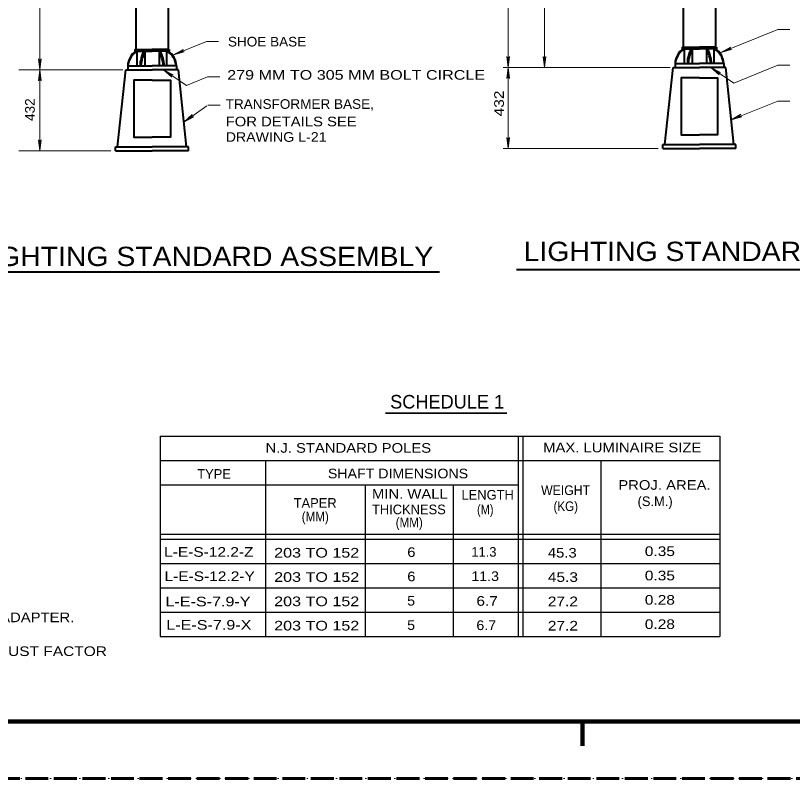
# Model space of a CAD drawing. Extents: x 312583 to 312854, y 144419 to 144597.
# Drawn here: x 312682.7 to 312743.9, y 144418.6 to 144478.7 of the extents above; entities that cross this region are included whole.
import ezdxf
from ezdxf.enums import TextEntityAlignment as Align

# ---------------------------------------------------------------- set-up
doc = ezdxf.new("R2010")
doc.units = 0
doc.header["$LTSCALE"] = 0.3
doc.linetypes.add('DOTTED', pattern=[1.5, 0.3, -1.2])
doc.linetypes.add('LONG_DASHED', pattern=[7.5, 6, -1.5])
for name, color, linetype, lineweight in [('1', 7, 'Continuous', 40), ('2', 7, 'Continuous', 13), ('63', 7, 'DOTTED', 13)]:
    doc.layers.add(name, color=color, linetype=linetype, lineweight=lineweight)

msp = doc.modelspace()

# ---------------------------------------------------------------- linework, layer by layer
at = {"layer": '1'}
for p, q in [((312692.1518, 144520.4576), (312692.1518, 144476.0523)), ((312694.7125, 144520.4576), (312694.7125, 144476.0523)), ((312735.288, 144495.6943), (312735.288, 144476.2363)), ((312737.8487, 144495.6943), (312737.8487, 144476.2363)), ((312692.0752, 144476.0523), (312693.4322, 144476.0523)), ((312692.0752, 144476.0523), (312692.0752, 144475.9373)), ((312694.7892, 144476.0523), (312693.4322, 144476.0523)), ((312694.7892, 144476.0523), (312694.7892, 144475.9373)), ((312735.2113, 144476.2363), (312736.5683, 144476.2363)), ((312735.2113, 144476.2363), (312735.2113, 144476.1213)), ((312735.2113, 144476.1213), (312736.5683, 144476.1213)), ((312735.3953, 144474.9636), (312735.3953, 144476.1213)), ((312736.0087, 144476.1213), (312736.0087, 144475.002)), ((312737.9253, 144476.2363), (312736.5683, 144476.2363)), ((312737.9253, 144476.1213), (312736.5683, 144476.1213)), ((312737.128, 144476.1213), (312737.128, 144475.002)), ((312737.7413, 144474.9636), (312737.7413, 144476.1213)), ((312737.9253, 144476.2363), (312737.9253, 144476.1213)), ((312692.0752, 144475.9373), (312693.4322, 144475.9373)), ((312692.2592, 144474.7796), (312692.2592, 144475.9373)), ((312692.8725, 144475.9373), (312692.8725, 144474.818)), ((312694.7892, 144475.9373), (312693.4322, 144475.9373)), ((312693.9918, 144475.9373), (312693.9918, 144474.818)), ((312694.6052, 144474.7796), (312694.6052, 144475.9373)), ((312691.5155, 144474.7796), (312693.4322, 144474.7796)), ((312691.5155, 144474.7796), (312691.5155, 144474.4576)), ((312695.3488, 144474.7796), (312693.4322, 144474.7796)), ((312695.3488, 144474.7796), (312695.3488, 144474.4576)), ((312734.6517, 144474.9636), (312736.5683, 144474.9636)), ((312734.6517, 144474.9636), (312734.6517, 144474.6416)), ((312738.485, 144474.9636), (312736.5683, 144474.9636)), ((312738.485, 144474.9636), (312738.485, 144474.6416)), ((312690.7182, 144468.3856), (312691.3545, 144474.4576)), ((312691.3545, 144474.4576), (312693.4322, 144474.4576)), ((312695.5098, 144474.4576), (312693.4322, 144474.4576)), ((312696.1462, 144468.3856), (312695.5098, 144474.4576)), ((312733.8543, 144468.5696), (312734.4907, 144474.6416)), ((312734.4907, 144474.6416), (312736.5683, 144474.6416)), ((312738.646, 144474.6416), (312736.5683, 144474.6416)), ((312739.2823, 144468.5696), (312738.646, 144474.6416)), ((312690.5572, 144468.3856), (312693.4322, 144468.3856)), ((312690.5572, 144468.0713), (312690.5572, 144468.3856)), ((312690.5572, 144468.0713), (312693.4322, 144468.0713)), ((312696.3072, 144468.3856), (312693.4322, 144468.3856)), ((312696.3072, 144468.0713), (312693.4322, 144468.0713)), ((312696.3072, 144468.0713), (312696.3072, 144468.3856)), ((312733.6933, 144468.5696), (312736.5683, 144468.5696)), ((312733.6933, 144468.2553), (312733.6933, 144468.5696)), ((312733.6933, 144468.2553), (312736.5683, 144468.2553)), ((312739.4433, 144468.5696), (312736.5683, 144468.5696)), ((312739.4433, 144468.2553), (312736.5683, 144468.2553)), ((312739.4433, 144468.2553), (312739.4433, 144468.5696))]:
    msp.add_line(p, q, dxfattribs=at)
at = {"layer": '1', "lineweight": 158}
for p, q in [((312616.5, 144423.0846), (312849, 144423.0846)), ((312727.35, 144421.1646), (312727.35, 144423.0846))]:
    msp.add_line(p, q, dxfattribs=at)
at = {"layer": '1'}
for points in [[(312693.4322, 144473.6296), (312691.9985, 144473.6296), (312691.9985, 144469.1523), (312693.4322, 144469.1523)], [(312693.4322, 144473.6296), (312694.8735, 144473.6296), (312694.8735, 144469.1523), (312693.4322, 144469.1523)], [(312736.5683, 144473.8136), (312735.127, 144473.8136), (312735.127, 144469.3363), (312736.5683, 144469.3363)], [(312736.5683, 144473.8136), (312738.002, 144473.8136), (312738.002, 144469.3363), (312736.5683, 144469.3363)]]:
    msp.add_lwpolyline(points, dxfattribs=at)
for centre, radius, start, end in [((312736.1161, 144474.907), 1.4657, 124.21849, 177.88724), ((312736.2591, 144474.748), 1.6218, 122.28719, 172.4519), ((312738.5681, 144474.79), 2.9635, 153.35491, 176.59885), ((312738.5681, 144474.79), 2.8836, 152.55593, 176.59975), ((312734.5679, 144474.79), 2.8836, 3.40025, 27.44407), ((312734.5679, 144474.79), 2.9635, 3.40115, 26.64509), ((312736.877, 144474.748), 1.6218, 7.5481, 57.71281), ((312737.0199, 144474.907), 1.4657, 2.11276, 55.78151), ((312693.1235, 144474.5631), 1.6218, 122.28719, 172.4519), ((312692.9806, 144474.7221), 1.4657, 124.21849, 177.88724), ((312695.4326, 144474.6051), 2.9635, 153.35491, 176.59885), ((312695.4326, 144474.6051), 2.8836, 152.55593, 176.59975), ((312691.4324, 144474.6051), 2.8836, 3.40025, 27.44407), ((312691.4324, 144474.6051), 2.9635, 3.40115, 26.64509), ((312693.7414, 144474.5631), 1.6218, 7.5481, 57.71281), ((312693.8844, 144474.7221), 1.4657, 2.11276, 55.78151), ((312692.9134, 144474.8161), 0.0399, 180, 270), ((312693.9516, 144474.8161), 0.0399, 270, 0), ((312736.0489, 144475.001), 0.0399, 180, 270), ((312737.0871, 144475.001), 0.0399, 270, 0)]:
    msp.add_arc(centre, radius, start, end, dxfattribs=at)
at = {"layer": '2'}
for p, q in [((312684.596, 144474.4576), (312684.596, 144558.791)), ((312721.4957, 144474.6416), (312721.4957, 144558.975)), ((312724.3707, 144474.6416), (312724.3707, 144520.6416)), ((312738.255, 144475.8223), (312742.7477, 144477.6316)), ((312742.7477, 144477.6316), (312743.706, 144477.6316)), ((312695.1188, 144475.6383), (312697.717, 144476.6847)), ((312697.717, 144476.6847), (312698.6753, 144476.6847)), ((312695.1188, 144475.6383), (312695.8855, 144476.06)), ((312695.8855, 144476.06), (312695.6708, 144475.8606)), ((312738.255, 144475.8223), (312739.0217, 144476.2516)), ((312738.255, 144475.8223), (312739.0983, 144476.0523)), ((312739.0217, 144476.2516), (312738.807, 144476.0446)), ((312739.0983, 144476.0523), (312738.807, 144476.0446)), ((312695.1188, 144475.6383), (312695.9622, 144475.8606)), ((312695.9622, 144475.8606), (312695.6708, 144475.8606)), ((312721.3883, 144475.508), (312721.4957, 144475.232)), ((312721.4957, 144474.6416), (312721.3883, 144475.508)), ((312721.603, 144475.508), (312721.4957, 144475.232)), ((312721.4957, 144474.6416), (312721.603, 144475.508)), ((312724.2633, 144475.508), (312724.3707, 144475.232)), ((312724.3707, 144474.6416), (312724.2633, 144475.508)), ((312724.478, 144475.508), (312724.3707, 144475.232)), ((312724.3707, 144474.6416), (312724.478, 144475.508)), ((312684.4887, 144475.324), (312684.596, 144475.048)), ((312684.596, 144474.4576), (312684.4887, 144475.324)), ((312684.7033, 144475.324), (312684.596, 144475.048)), ((312684.596, 144474.4576), (312684.7033, 144475.324)), ((312739.2747, 144473.415), (312742.7477, 144474.818)), ((312742.7477, 144474.818), (312743.706, 144474.818)), ((312691.1322, 144474.4576), (312682.9368, 144474.4576)), ((312684.596, 144474.4576), (312684.4887, 144473.5913)), ((312684.596, 144468.0713), (312684.596, 144474.4576)), ((312684.596, 144474.4576), (312684.7033, 144473.5913)), ((312696.1385, 144473.231), (312694.3292, 144474.4576)), ((312694.3292, 144474.4576), (312694.9808, 144473.8826)), ((312694.3292, 144474.4576), (312695.1035, 144474.059)), ((312694.9808, 144473.8826), (312694.8122, 144474.128)), ((312695.1035, 144474.059), (312694.8122, 144474.128)), ((312734.2683, 144474.6416), (312721.1123, 144474.6416)), ((312721.4957, 144474.6416), (312721.3883, 144473.7753)), ((312721.4957, 144468.2553), (312721.4957, 144474.6416)), ((312721.4957, 144474.6416), (312721.603, 144473.7753)), ((312739.2747, 144473.415), (312737.4653, 144474.6416)), ((312737.4653, 144474.6416), (312738.117, 144474.0666)), ((312737.4653, 144474.6416), (312738.2397, 144474.243)), ((312738.117, 144474.0666), (312737.9483, 144474.312)), ((312738.2397, 144474.243), (312737.9483, 144474.312)), ((312684.4887, 144473.5913), (312684.596, 144473.8673)), ((312684.7033, 144473.5913), (312684.596, 144473.8673)), ((312696.1385, 144473.231), (312697.8078, 144473.9053)), ((312697.8078, 144473.9053), (312698.7661, 144473.9053)), ((312721.3883, 144473.7753), (312721.4957, 144474.0513)), ((312721.603, 144473.7753), (312721.4957, 144474.0513)), ((312697.8398, 144471.6784), (312698.7981, 144471.6784)), ((312739.0753, 144470.517), (312742.7477, 144471.9966)), ((312742.7477, 144471.9966), (312743.706, 144471.9966)), ((312695.9392, 144470.333), (312697.7438, 144471.6215)), ((312695.9392, 144470.333), (312696.5908, 144470.9233)), ((312695.9392, 144470.333), (312696.7135, 144470.747)), ((312696.5908, 144470.9233), (312696.4298, 144470.6703)), ((312696.7135, 144470.747), (312696.4298, 144470.6703)), ((312739.0753, 144470.517), (312739.842, 144470.9463)), ((312739.0753, 144470.517), (312739.9187, 144470.747)), ((312739.842, 144470.9463), (312739.6273, 144470.7393)), ((312739.9187, 144470.747), (312739.6273, 144470.7393)), ((312684.4887, 144468.9376), (312684.596, 144468.6616)), ((312684.596, 144468.0713), (312684.4887, 144468.9376)), ((312684.7033, 144468.9376), (312684.596, 144468.6616)), ((312684.596, 144468.0713), (312684.7033, 144468.9376)), ((312721.3883, 144469.1216), (312721.4957, 144468.8456)), ((312721.4957, 144468.2553), (312721.3883, 144469.1216)), ((312721.603, 144469.1216), (312721.4957, 144468.8456)), ((312721.4957, 144468.2553), (312721.603, 144469.1216)), ((312690.1738, 144468.0713), (312682.9368, 144468.0713)), ((312733.31, 144468.2553), (312721.1123, 144468.2553))]:
    msp.add_line(p, q, dxfattribs=at)
at = {"layer": '2', "lineweight": 40}
for p, q in [((312679.0175, 144458.5382), (312716.0815, 144458.5382)), ((312722.1455, 144458.7223), (312759.4221, 144458.7223))]:
    msp.add_line(p, q, dxfattribs=at)
at = {"layer": '2', "lineweight": 35}
msp.add_line((312711.8273, 144447.398), (312721.3945, 144447.398), dxfattribs=at)
at = {"layer": '2', "lineweight": 25}
for p, q in [((312694.0795, 144445.5734), (312738.1839, 144445.5734)), ((312722.2755, 144445.5734), (312722.2755, 144429.7867)), ((312722.6589, 144445.5734), (312722.6589, 144429.7867)), ((312738.1839, 144445.5734), (312738.1839, 144429.7867)), ((312694.0795, 144443.6567), (312738.1839, 144443.6567)), ((312702.3702, 144443.6567), (312702.3702, 144429.7867)), ((312728.7922, 144443.6567), (312728.7922, 144429.7867)), ((312694.0795, 144441.74), (312722.2755, 144441.74)), ((312710.2366, 144441.74), (312710.2366, 144429.7867)), ((312717.1584, 144441.74), (312717.1584, 144429.7867)), ((312694.0795, 144437.8367), (312738.1839, 144437.8367)), ((312694.0795, 144437.4534), (312738.1839, 144437.4534)), ((312694.0795, 144435.5367), (312738.1839, 144435.5367)), ((312694.0795, 144433.62), (312738.1839, 144433.62)), ((312694.0795, 144431.7034), (312738.1839, 144431.7034))]:
    msp.add_line(p, q, dxfattribs=at)
msp.add_lwpolyline([(312694.0795, 144445.5734), (312694.0795, 144429.7867), (312738.1839, 144429.7867)], dxfattribs=at)
at = {"layer": '63', "linetype": 'LONG_DASHED', "lineweight": 60}
msp.add_line((312851.75, 144418.5846), (312583.526, 144418.5846), dxfattribs=at)
at = {"layer": '63'}
msp.add_lwpolyline([(312601.2, 144418.5846), (312853.5, 144418.5846), (312853.5, 144596.7846)], dxfattribs=at)

# ---------------------------------------------------------------- texts
at = {"layer": '2'}
for s, width, p in [('SHOE BASE', 1.05, (312699.4129, 144476.2948)), ('279 MM TO 305 MM BOLT CIRCLE', 1.25, (312699.3508, 144473.6743)), ('TRANSFORMER BASE,', 1.05, (312699.2351, 144471.3784)), ('FOR DETAILS SEE', 1.15, (312699.2351, 144469.9984)), ('DRAWING L-21', 1.1, (312699.2351, 144468.7784)), ('N.J. STANDARD POLES', 1.15, (312702.3742, 144444.2652)), ('MAX. LUMINAIRE SIZE', 1.15, (312724.2534, 144444.2959)), ('SHAFT DIMENSIONS', 1.1, (312707.2873, 144442.247)), ('WEIGHT', 0.95, (312724.0946, 144440.9302)), ('PROJ. AREA.', 1.15, (312730.1783, 144441.3443)), ('MIN. WALL', 1.15, (312710.7638, 144440.6361)), ('(KG)', 0.9, (312725.0712, 144439.6691)), ('(M)', 0.85, (312719.0475, 144439.4209)), ('(MM)', 0.9, (312705.2283, 144438.8535)), ('(MM)', 0.9, (312712.6341, 144438.3925)), ('L-E-S-12.2-Z', 1.2, (312694.3815, 144436.0647)), ('203 TO 152', 1.25, (312703.053, 144436.0015)), ('6 ', 1.15, (312713.5442, 144436.0494)), ('45.3', 1.15, (312724.6243, 144435.9986)), ('0.35', 1.2, (312732.2677, 144436.1204)), ('11.3 ', 1.1, (312718.5978, 144434.1529)), ('0.35', 1.2, (312732.2677, 144434.2037)), ('L-E-S-12.2-Y', 1.2, (312694.413, 144434.1481)), ('203 TO 152', 1.25, (312703.053, 144434.0848)), ('6 ', 1.15, (312713.5442, 144434.1327)), ('45.3 ', 1.2, (312724.6243, 144434.0819)), ('L-E-S-7.9-Y', 1.25, (312694.4876, 144432.1547)), ('203 TO 152', 1.25, (312703.053, 144432.1682)), ('5 ', 1.1, (312713.539, 144432.2161)), ('6.7 ', 1.2, (312718.9943, 144432.2007)), ('27.2 ', 1.2, (312724.6243, 144432.1652)), ('0.28', 1.2, (312732.2677, 144432.2871)), ('THE YOKE SHALL BE DESIGNED TO BE INSTALLED ON MOUNTING ADAPTER.', 1.15, (312643.5976, 144430.9051)), ('L-E-S-7.9-X', 1.25, (312694.5554, 144430.3147)), ('203 TO 152', 1.25, (312703.053, 144430.2515)), ('5 ', 1.1, (312713.539, 144430.2994)), ('6.7', 1.1, (312718.9943, 144430.2841)), ('27.2 ', 1.2, (312724.6243, 144430.2486)), ('0.28', 1.2, (312732.2677, 144430.3704)), ('ADJUSTMENT SUCH THAT WIND LOAD OF 129 KM/H WITH A 1.3 GUST FACTOR ', 1.2, (312643.5976, 144428.2371))]:
    msp.add_text(s, height=0.76, dxfattribs=dict(at, width=width)).set_placement(p)
for s, width, p in [('432 ', 1.2, (312721.1579, 144470.7851)), ('432', 1.05, (312684.1874, 144470.4239))]:
    msp.add_text(s, height=0.76, rotation=90, dxfattribs=dict(at, width=width)).set_placement(p)
at = {"layer": '2', "width": 1.1}
for p in [(312740.7958, 144459.3818), (312697.5179, 144458.9849)]:
    msp.add_text('LIGHTING STANDARD ASSEMBLY', height=1.52, dxfattribs=at).set_placement(p, align=Align.CENTER)
at = {"layer": '2'}
msp.add_text('SCHEDULE 1', height=1.07, dxfattribs=at).set_placement((312716.6904, 144447.7513), align=Align.CENTER)
for s, p in [('TYPE', (312696.9917, 144442.2116)), ('LENGTH', (312717.8215, 144440.5699)), ('TAPER', (312704.5929, 144439.9267)), ('(S.M.)', (312731.6974, 144440.0592)), ('THICKNESS', (312710.7638, 144439.4161)), ('11.3', (312718.5978, 144436.0696))]:
    msp.add_text(s, height=0.76, dxfattribs=at).set_placement(p)

doc.saveas('drawing.dxf')
